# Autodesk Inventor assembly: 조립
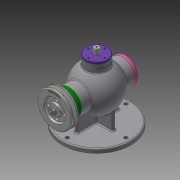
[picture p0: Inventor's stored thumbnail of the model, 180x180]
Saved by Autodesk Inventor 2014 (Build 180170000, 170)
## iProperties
Created: 2020-08
Part Number: 조립
Document SubType Name: Assembly
Designer: kh
Author: kh
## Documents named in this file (18)
- C:\Users\kh\Desktop\700806V1026\조립.iam
- C:\Users\kh\Desktop\700806V1026\본체.ipt
- C:\Users\kh\Desktop\700806V1026\V-벨트풀리.ipt
- C:\Users\kh\Desktop\700806V1026\너트 M8.ipt
- C:\Users\kh\Desktop\700806V1026\뒤커버.ipt
- C:\Users\kh\Desktop\700806V1026\멈춤링 15x1.ipt
- C:\Users\kh\Desktop\700806V1026\멈춤링 35x1.6.ipt
- 멈춤링 35x1.6.ipt
- C:\Users\kh\Desktop\700806V1026\베어링 6202.ipt
- 베어링 6202.ipt
- C:\Users\kh\Desktop\700806V1026\볼트 M4.ipt
- C:\Users\kh\Desktop\700806V1026\상부커버.ipt
- C:\Users\kh\Desktop\700806V1026\슬라이드.ipt
- C:\Users\kh\Desktop\700806V1026\앞커버.ipt
- C:\Users\kh\Desktop\700806V1026\오일 실 15 30 7.ipt
- C:\Users\kh\Desktop\700806V1026\칼라.ipt
- C:\Users\kh\Desktop\700806V1026\키 3x3x12.ipt
- C:\Users\kh\Desktop\700806V1026\편심축.ipt
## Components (1 placed, 1 different names)
1. V-벨트풀리:1 — Insert:13, Mate:4, Insert:14
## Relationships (3: Insert 2, Mate 1)
- Insert:13: V-벨트풀리:1
- Mate:4: V-벨트풀리:1
- Insert:14: V-벨트풀리:1
